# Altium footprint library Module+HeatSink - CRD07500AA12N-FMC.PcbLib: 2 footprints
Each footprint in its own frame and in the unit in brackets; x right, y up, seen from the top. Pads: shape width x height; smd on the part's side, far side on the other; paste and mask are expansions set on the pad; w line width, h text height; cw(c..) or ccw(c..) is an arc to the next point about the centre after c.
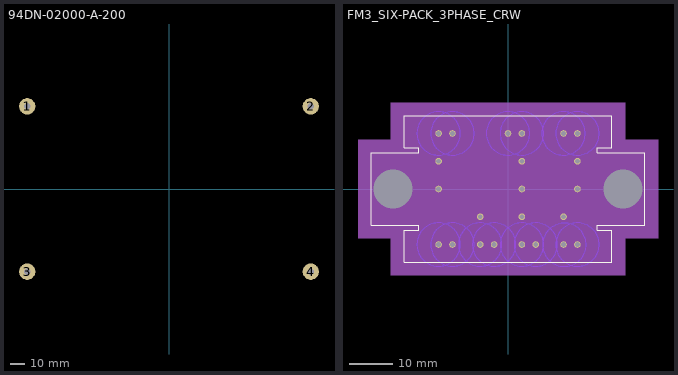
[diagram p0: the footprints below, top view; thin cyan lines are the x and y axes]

## 94DN-02000-A-200 [mm]
pads (4):
  round 11 hole 4.5: 1(-95.25,55.5) 2(95.25,55.5) 3(-95.25,-55.5) 4(95.25,-55.5)
3D body "H S Marston 94DN-02000-A-200 + Standoffs.STEP": height 52, standoff 0, extent -99.973,-61.507 100.027,61.493

## FM3_SIX-PACK_3PHASE_CRW [mm]
pads (25):
  round 1.524 hole 1.1: DC+_1(-6.4,-6.4) DC+_2(3.2,-6.4) DC+_3(12.8,-6.4) DC-1(-16,0) DC-2(3.2,0) DC-3(16,0) G1(-12.8,-12.8) G2(-16,12.8) G3(-3.2,-12.8) G4(3.2,12.8) G5(6.4,-12.8) G6(16,12.8) NTC1(12.8,-12.8) NTC2(16,-12.8) S1(-16,-12.8) S2(-12.8,12.8) S3(-6.4,-12.8) S4(0,12.8) S5(3.2,-12.8) S6(12.8,12.8) U(-16,6.4) V(3.2,6.4) W(16,6.4)
  round 0 hole 9 unplated: MH1(-26.5,0) MH2(26.5,0)
Bottom Layer keep-out:
  circle w0.254: c-16,-12.8 r5
  circle w0.254: c-12.8,-12.8 r5
  circle w0.254: c-6.4,-12.8 r5
  circle w0.254: c-3.2,-12.8 r5
  circle w0.254: c3.2,-12.8 r5
  circle w0.254: c6.4,-12.8 r5
  circle w0.254: c12.997,-12.859 r5
  circle w0.254: c16,-12.8 r5
  circle w0.254: c16,12.8 r5
  circle w0.254: c12.8,12.8 r5
  circle w0.254: c3.2,12.8 r5
  circle w0.254: c0,12.8 r5
  circle w0.254: c-12.8,12.8 r5
  circle w0.254: c-16,12.8 r5
Top Overlay:
  lines w0.152: -31.521,-8.331 -31.521,8.331 -20.625,8.331 -20.625,9.563 -23.927,9.563 -23.927,16.878 23.927,16.878 23.927,9.563 20.625,9.563 20.625,8.331 31.521,8.331 31.521,-8.331 20.625,-8.331 20.625,-9.563 23.927,-9.563 23.927,-16.878 -23.927,-16.878 -23.927,-9.563 -20.625,-9.563 -20.625,-8.331 -31.521,-8.331
Bottom Courtyard:
  text "Default Padstyle: EX60Y60D43P0" at -9.525,-21.831 h1.27
Bottom 3D Body:
  region: 26.975,19.926 -26.975,19.926 -26.975,11.379 -34.569,11.379 -34.569,-11.379 -26.975,-11.379 -26.975,-19.926 26.975,-19.926 26.975,-11.379 34.569,-11.379 34.569,11.379 26.975,11.379
Top Designator:
  text ".Designator" at 7.618,-0.694 h1.52
Mechanical 13:
  drawing of 27 lines, arcs and shapes, not listed
Mechanical 15:
  region: 20.752,-9.436 20.752,-8.458 31.648,-8.458 31.648,8.458 20.752,8.458 20.752,9.436 24.054,9.436 24.054,17.005 -24.054,17.005 -24.054,9.436 -20.752,9.436 -20.752,8.458 -31.648,8.458 -31.648,-8.458 -20.752,-8.458 -20.752,-9.436 -24.054,-9.436 -24.054,-17.005 24.054,-17.005 24.054,-9.436
  lines w0.152: -31.648,-8.458 -31.648,8.458 -20.752,8.458 -20.752,9.436 -24.054,9.436 -24.054,17.005 24.054,17.005 24.054,9.436 20.752,9.436 20.752,8.458 31.648,8.458 31.648,-8.458 20.752,-8.458 20.752,-9.436 24.054,-9.436 24.054,-17.005 -24.054,-17.005 -24.054,-9.436 -20.752,-9.436 -20.752,-8.458 -31.648,-8.458
3D body "McMaster-Carr 93070A095 - Alternative.STEP": height -7.7, standoff -16.5, extent -30,-3.5 -23,3.5
3D body "McMaster-Carr 93070A095 - Alternative.STEP": height -7.7, standoff -16.5, extent 23,-3.5 30,3.5
3D body: height 0.25, standoff 0, extent 0,0 0.254,0.254
3D body "CCB0xxM12FM3(Six_Pack)_External_POD_20200723_Branded_Origin.STEP": height 11.98, standoff -4.42, extent -31.4,-16.9 31.4,16.9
